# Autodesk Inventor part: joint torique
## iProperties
Shininess: 64.0
Length Units: 11269
Angle Units: 11279
Time Units: 11290
Mass Units: 11283
Length Display Precision: 3
Angle Display Precision: 2
Compacted: True
Part Number: joint torique
Document SubType Name: Modeling
Created: 2005-01
Material: Par défaut
Designer: Flavien MARTY
Density: 0.0
Volumn: 0.0
Area: 0.0
PropertySet Name: Model Information
Control State: 0
Master: False
Checked Out: False
Norme de conversion: STEP AP203
Nom du fichier: joint torique.STEP
Préprocesseur: SolidWorks 2001039
Postprocesseur: Build: Release: 6 RTM Build: 90b - Date: Tue 09/24/2002
Unités envoyées: MILLIMETERS
Incertitude: 0.0
Author: Flavien MARTY
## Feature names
1. Base1
